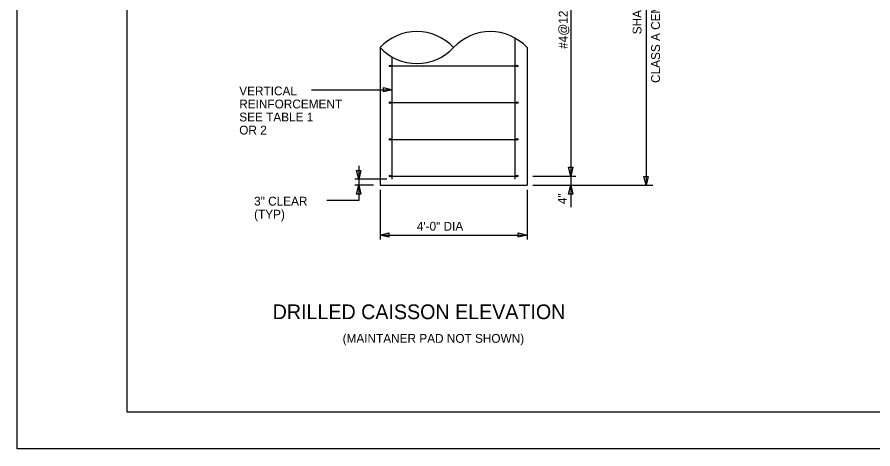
# Model space of a CAD drawing. Extents: x 1299104.6 to 1299141.4, y 239713.3 to 239735.3.
# Drawn here: x 1299104.62 to 1299116.27, y 239713.27 to 239719.15 of the extents above; entities that cross this region are included whole.
import ezdxf

# ---------------------------------------------------------------- set-up
doc = ezdxf.new("R2010")
doc.units = 0
for name, color, linetype in [('DIM TXT', 7, 'Continuous'), ('GS_plotshape_p', 7, 'Continuous'), ('Level 1', 7, 'Continuous'), ('Level 3', 7, 'Continuous'), ('Level 8', 7, 'Continuous')]:
    doc.layers.add(name, color=color, linetype=linetype)

msp = doc.modelspace()

# ---------------------------------------------------------------- linework, layer by layer
at = {"layer": 'GS_plotshape_p'}
msp.add_lwpolyline([(1299104.622, 239735.273), (1299138.622, 239735.273), (1299138.622, 239713.273), (1299104.622, 239713.273)], close=True, dxfattribs=at)
at = {"layer": 'Level 1'}
msp.add_lwpolyline([(1299138.122, 239713.773), (1299106.122, 239713.773), (1299106.122, 239734.773), (1299138.122, 239734.773)], close=True, dxfattribs=at)
at = {"layer": 'Level 3'}
for p, q in [((1299111.398, 239716.944), (1299111.398, 239718.866)), ((1299109.562, 239718.736), (1299109.562, 239716.861)), ((1299111.562, 239718.736), (1299111.562, 239716.861)), ((1299109.727, 239716.944), (1299109.727, 239718.606)), ((1299109.698, 239718.486), (1299111.427, 239718.486)), ((1299109.698, 239717.986), (1299111.427, 239717.986)), ((1299109.698, 239717.486), (1299111.427, 239717.486)), ((1299109.698, 239716.986), (1299111.417, 239716.986)), ((1299109.562, 239716.861), (1299111.562, 239716.861))]:
    msp.add_line(p, q, dxfattribs=at)
for centre in [(1299109.698, 239718.486), (1299111.427, 239718.486), (1299109.698, 239717.986), (1299111.427, 239717.986), (1299109.698, 239717.486), (1299111.427, 239717.486), (1299109.698, 239716.986), (1299111.427, 239716.986)]:
    msp.add_circle(centre, 0.0104, dxfattribs=at)
for centre, start, end in [((1299110.062, 239718.271), 42.8709, 137.1291), ((1299111.062, 239718.271), 42.8709, 137.1291), ((1299110.062, 239719.2), 222.8709, 317.1291)]:
    msp.add_arc(centre, 0.682, start, end, dxfattribs=at)
at = {"layer": 'Level 8'}
for p, q in [((1299112.155, 239722.756), (1299112.155, 239716.561)), ((1299113.18, 239722.361), (1299113.18, 239716.861)), ((1299108.63, 239718.162), (1299109.727, 239718.162)), ((1299109.271, 239717.126), (1299109.271, 239716.654)), ((1299109.653, 239716.944), (1299109.219, 239716.944)), ((1299111.641, 239716.986), (1299112.224, 239716.986)), ((1299109.471, 239716.861), (1299109.219, 239716.861)), ((1299109.562, 239716.801), (1299109.562, 239716.123)), ((1299111.562, 239716.801), (1299111.562, 239716.123)), ((1299111.641, 239716.861), (1299113.272, 239716.861)), ((1299112.037, 239716.861), (1299112.556, 239716.861)), ((1299109.271, 239716.654), (1299108.836, 239716.654)), ((1299109.562, 239716.183), (1299111.562, 239716.183))]:
    msp.add_line(p, q, dxfattribs=at)
for points in [[(1299109.607, 239718.192), (1299109.727, 239718.162), (1299109.607, 239718.132)], [(1299109.301, 239717.064), (1299109.271, 239716.944), (1299109.241, 239717.064)], [(1299112.185, 239717.106), (1299112.155, 239716.986), (1299112.125, 239717.106)], [(1299113.21, 239716.981), (1299113.18, 239716.861), (1299113.15, 239716.981)], [(1299109.241, 239716.741), (1299109.271, 239716.861), (1299109.301, 239716.741)], [(1299112.125, 239716.741), (1299112.155, 239716.861), (1299112.185, 239716.741)], [(1299109.682, 239716.153), (1299109.562, 239716.183), (1299109.682, 239716.213)], [(1299111.442, 239716.213), (1299111.562, 239716.183), (1299111.442, 239716.153)]]:
    msp.add_lwpolyline(points, close=True, dxfattribs=at)

# ---------------------------------------------------------------- texts
at = {"layer": 'DIM TXT'}
for s, p in [('CLASS A CEMENT CONCRETE', (1299113.37, 239718.254)), ('SHAFT LENGTH', (1299113.118, 239718.916)), ('#4@12" MIN', (1299112.112, 239718.718)), ('4"', (1299112.101, 239716.604))]:
    msp.add_text(s, height=0.12, rotation=90, dxfattribs=at).set_placement(p)
for s, height, p in [('VERTICAL', 0.12, (1299107.645, 239718.085)), ('REINFORCEMENT', 0.12, (1299107.645, 239717.907)), ('SEE TABLE 1', 0.12, (1299107.645, 239717.73)), ('OR 2', 0.12, (1299107.645, 239717.552)), ('3" CLEAR', 0.12, (1299107.847, 239716.585)), ('(TYP)', 0.12, (1299107.847, 239716.407)), ('4\'-0" DIA', 0.12, (1299110.061, 239716.243)), ('DRILLED CAISSON ELEVATION', 0.2, (1299108.1, 239715.039)), ('(MAINTANER PAD NOT SHOWN)', 0.12, (1299109.052, 239714.717))]:
    msp.add_text(s, height=height, dxfattribs=at).set_placement(p)

doc.saveas('drawing.dxf')
